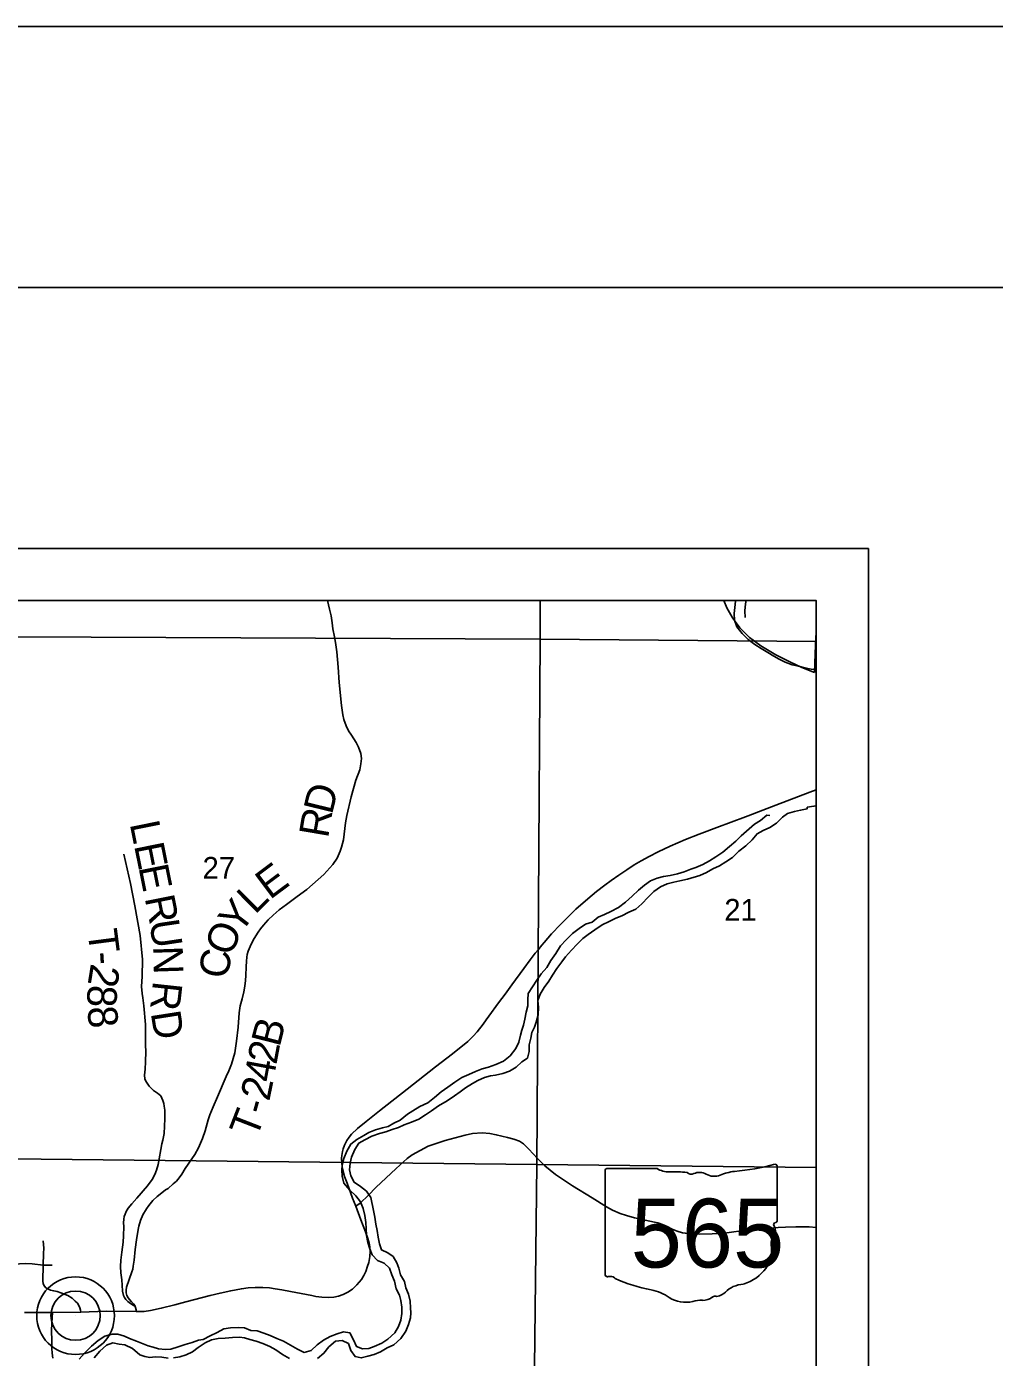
# Model space of a CAD drawing. Extents: x 0 to 34, y 0 to 22.
# Drawn here: x 7.387 to 9.241, y 19.45 to 22 of the extents above; entities that cross this region are included whole.
import ezdxf

# ---------------------------------------------------------------- set-up
doc = ezdxf.new("R2010")
doc.units = 0
for name, color, linetype in [('GM_X_Corporation', 7, 'Continuous'), ('GM_X_County_Road', 7, 'Continuous'), ('GM_X_Major_River', 7, 'Continuous'), ('GM_X_Section_Text', 7, 'Continuous'), ('GM_X_State_Route', 7, 'Continuous'), ('GM_X_State_Shield', 7, 'Continuous'), ('GM_X_Township_Road', 7, 'Continuous'), ('GM_X_Township_Road_Text', 7, 'Continuous'), ('GM_X_Township_Text', 7, 'Continuous'), ('GM_X_Unincorporated', 7, 'Continuous'), ('GM_X_Unincorporated_Location', 7, 'Continuous'), ('SH_Border', 7, 'Continuous'), ('SH_Cut_Line', 7, 'Continuous'), ('SH_Data', 7, 'Continuous')]:
    doc.layers.add(name, color=color, linetype=linetype)

msp = doc.modelspace()

# ---------------------------------------------------------------- linework, layer by layer
at = {"layer": 'GM_X_Corporation'}
for points in [[(8.371, 20.9), (7.3671, 20.9), (7.3663, 20.8308), (8.3706, 20.8258)], [(8.9, 20.8218), (8.9, 20.9), (8.371, 20.9), (8.3706, 20.8258)], [(8.3706, 20.8258), (8.3645, 19.8193), (7.3548, 19.8302), (7.3663, 20.8308)], [(8.9, 19.8133), (8.9, 20.8218), (8.3706, 20.8258), (8.3645, 19.8193)], [(8.3645, 19.8193), (8.353, 18.8213), (7.3418, 18.8315), (7.3548, 19.8302)], [(8.9, 18.8136), (8.9, 19.8133), (8.3645, 19.8193), (8.353, 18.8213)]]:
    msp.add_lwpolyline(points, close=True, dxfattribs=at)
at = {"layer": 'GM_X_County_Road'}
msp.add_lwpolyline([(7.4367, 19.4485), (7.4357, 19.4575), (7.4351, 19.4669), (7.4346, 19.482), (7.4342, 19.5004), (7.4347, 19.515), (7.4359, 19.5357)], dxfattribs=at)
at = {"layer": 'GM_X_Major_River'}
for points in [[(8.7457, 20.9), (8.7454, 20.8989), (8.7437, 20.8867), (8.7423, 20.8753), (8.7432, 20.8624), (8.7475, 20.8496), (8.7578, 20.8372), (8.7693, 20.8255), (8.7819, 20.8158), (8.7945, 20.8084), (8.8071, 20.8005), (8.8189, 20.7935), (8.8288, 20.7879), (8.8406, 20.7823), (8.8535, 20.7771), (8.866, 20.7742), (8.8778, 20.7713)], [(8.7636, 20.8676), (8.7627, 20.8805), (8.764, 20.8938), (8.7657, 20.9)], [(8.8778, 20.7713), (8.8903, 20.7688), (8.9, 20.7681)], [(8.8822, 20.504), (8.8954, 20.506), (8.9, 20.5068)], [(8.8112, 20.4884), (8.8052, 20.4891), (8.7932, 20.4788), (8.7815, 20.4714), (8.756, 20.4492), (8.7459, 20.4388), (8.7339, 20.4288), (8.7208, 20.4181), (8.7073, 20.4088), (8.6952, 20.4015), (8.6825, 20.3942), (8.6693, 20.3884), (8.6595, 20.3856), (8.647, 20.3802), (8.6338, 20.3766), (8.6199, 20.373), (8.6074, 20.3714), (8.5953, 20.3682), (8.5825, 20.3628), (8.5709, 20.3547), (8.5592, 20.3451), (8.5472, 20.3336), (8.5341, 20.3221), (8.5206, 20.3121), (8.5059, 20.304), (8.4939, 20.2982), (8.4818, 20.2935), (8.4702, 20.2839), (8.4578, 20.2799), (8.4457, 20.2719), (8.433, 20.2619), (8.4206, 20.25), (8.4098, 20.2381), (8.4005, 20.224), (8.3912, 20.2102), (8.3834, 20.1972), (8.3729, 20.1846), (8.3643, 20.1724), (8.348, 20.1472), (8.3473, 20.1351), (8.3471, 20.1237), (8.3442, 20.1111), (8.3413, 20.0978), (8.3388, 20.0864), (8.3359, 20.0769), (8.3333, 20.067), (8.3297, 20.0537), (8.3241, 20.0415), (8.3133, 20.0277), (8.3002, 20.0177), (8.2855, 20.0108), (8.2719, 20.0057), (8.2598, 20.0025), (8.2466, 19.9978), (8.2338, 19.992), (8.2207, 19.9858), (8.2075, 19.977), (8.194, 19.9673), (8.1809, 19.9585), (8.1685, 19.9477), (8.1553, 19.9377), (8.1403, 19.9304), (8.1264, 19.9219), (8.1166, 19.9157), (8.1027, 19.9042), (8.0903, 19.8987), (8.0794, 19.8925), (8.0688, 19.8894), (8.0549, 19.8858), (8.0424, 19.8804), (8.0327, 19.875), (8.0191, 19.8673), (8.0079, 19.8584), (8.0001, 19.8447), (7.9945, 19.8306), (7.9913, 19.8188), (7.9906, 19.8086), (7.9911, 19.7968), (7.9947, 19.7836), (8.0058, 19.7704), (8.0173, 19.7595), (8.0261, 19.7479), (8.0315, 19.735), (8.0347, 19.7218), (8.0364, 19.7085), (8.0373, 19.6964), (8.0382, 19.6831), (8.0402, 19.6699), (8.0441, 19.6578), (8.0488, 19.6461), (8.0591, 19.6352), (8.072, 19.63), (8.082, 19.621), (8.0867, 19.6082), (8.0913, 19.5957), (8.0945, 19.5813), (8.1011, 19.5689), (8.1039, 19.5587), (8.1059, 19.5462), (8.1056, 19.5337), (8.1035, 19.5211)], [(8.0998, 19.6208), (8.0963, 19.631), (8.0889, 19.6431), (8.0786, 19.6498), (8.0665, 19.6558), (8.0629, 19.6675), (8.0605, 19.68), (8.0585, 19.6928), (8.0557, 19.7049), (8.054, 19.7186), (8.0513, 19.7311), (8.0464, 19.756), (8.0376, 19.7685), (8.0265, 19.7771), (8.0143, 19.7853), (8.0078, 19.7977), (8.0054, 19.8091), (8.0064, 19.822), (8.0093, 19.8334), (8.0155, 19.8483), (8.023, 19.8605), (8.035, 19.8667), (8.0482, 19.8736), (8.0629, 19.8787), (8.075, 19.8819), (8.0874, 19.8862), (8.0995, 19.8905), (8.1104, 19.8955), (8.124, 19.9002), (8.1383, 19.9064), (8.1511, 19.9145), (8.1623, 19.9219), (8.1762, 19.9315), (8.1924, 19.9411), (8.2063, 19.9508), (8.2176, 19.9589), (8.2277, 19.9662), (8.2408, 19.9746), (8.251, 19.9804), (8.2638, 19.9859), (8.2755, 19.9894), (8.2853, 19.9907), (8.2989, 19.9935), (8.3121, 19.9982), (8.3249, 20.0062), (8.3354, 20.0158), (8.3463, 20.0232), (8.3495, 20.0361), (8.3494, 20.0486), (8.3527, 20.0612), (8.3548, 20.0726), (8.36, 20.0825), (8.3633, 20.092), (8.3669, 20.1061), (8.3675, 20.1205), (8.3666, 20.1337), (8.3707, 20.1455), (8.3785, 20.1585), (8.3871, 20.1707), (8.3945, 20.1822), (8.4027, 20.1952), (8.412, 20.2078), (8.4191, 20.2173), (8.4311, 20.23), (8.4415, 20.2415), (8.4528, 20.2522), (8.4625, 20.2599), (8.4753, 20.2691), (8.4896, 20.2788), (8.5027, 20.2853), (8.5155, 20.2912), (8.5276, 20.2962), (8.5408, 20.3028), (8.554, 20.3086), (8.5656, 20.3186), (8.5775, 20.3316), (8.5884, 20.3428), (8.6015, 20.3516), (8.614, 20.3571), (8.6268, 20.3602), (8.6385, 20.363), (8.6529, 20.3662), (8.677, 20.3733), (8.6898, 20.3787), (8.7018, 20.386), (8.7143, 20.3915), (8.7267, 20.3996), (8.7394, 20.4077), (8.7514, 20.4196), (8.7649, 20.4303), (8.7773, 20.4418), (8.7866, 20.4533), (8.7979, 20.4595), (8.8107, 20.4649), (8.8235, 20.4734), (8.8351, 20.4853), (8.8449, 20.4922), (8.8581, 20.4958), (8.8698, 20.4982), (8.8822, 20.5009), (8.8822, 20.504)], [(7.9442, 19.4474), (7.9562, 19.4578), (7.9659, 19.47), (7.9787, 19.4808), (7.9912, 19.482), (8.0033, 19.4761), (8.008, 19.4629), (8.0161, 19.4512), (8.0279, 19.4487), (8.0403, 19.4518), (8.0524, 19.4554), (8.0648, 19.4604), (8.0776, 19.4681), (8.0904, 19.4736), (8.1039, 19.4859), (8.1136, 19.5), (8.1184, 19.5129), (8.122, 19.5255), (8.1227, 19.535), (8.1222, 19.5445), (8.1217, 19.5574), (8.1181, 19.571), (8.1134, 19.5827), (8.1106, 19.5952), (8.1029, 19.608), (8.0998, 19.6208)], [(8.1035, 19.5211), (8.0995, 19.509), (8.0924, 19.4967), (8.0789, 19.4845), (8.0673, 19.4771), (8.0526, 19.4705), (8.0424, 19.4666), (8.0303, 19.4661), (8.0185, 19.4706), (8.0131, 19.4834), (8.0061, 19.4966), (7.9936, 19.4987), (7.9816, 19.4948), (7.968, 19.4897), (7.9556, 19.4828), (7.9436, 19.4739), (7.9316, 19.4628), (7.9184, 19.4593), (7.9054, 19.4652), (7.8925, 19.473), (7.8788, 19.4805), (7.8659, 19.4856), (7.8533, 19.4919), (7.8411, 19.4964), (7.8282, 19.5004), (7.8161, 19.5014), (7.8043, 19.5066), (7.7918, 19.5068), (7.7775, 19.5063), (7.7642, 19.5043), (7.7514, 19.4973), (7.7383, 19.4911), (7.7247, 19.4838), (7.7157, 19.4825), (7.7036, 19.4782), (7.6904, 19.4747), (7.6772, 19.47), (7.6629, 19.4657), (7.653, 19.4648), (7.6394, 19.4662), (7.6291, 19.4691), (7.6197, 19.472), (7.6102, 19.4757), (7.5969, 19.4805), (7.5839, 19.4861), (7.5744, 19.4905), (7.5615, 19.4942), (7.5502, 19.4944), (7.5362, 19.4901), (7.5234, 19.482), (7.5111, 19.4713), (7.4972, 19.4578), (7.4875, 19.446)], [(7.668, 19.4486), (7.6801, 19.4507), (7.6921, 19.4546), (7.7045, 19.4604), (7.7151, 19.4685), (7.729, 19.4774), (7.741, 19.4832), (7.7538, 19.4856), (7.7671, 19.4865), (7.7814, 19.4878), (7.7947, 19.4883), (7.8042, 19.4873), (7.814, 19.4839), (7.8262, 19.4807), (7.8395, 19.4763), (7.8524, 19.4707), (7.8642, 19.464), (7.8768, 19.4554), (7.8905, 19.4476)], [(7.5162, 19.4489), (7.527, 19.4619), (7.5394, 19.4731), (7.5515, 19.4778), (7.5636, 19.4752), (7.5746, 19.4738), (7.5894, 19.4668), (7.6036, 19.4548), (7.6131, 19.4515), (7.6229, 19.4493), (7.6331, 19.4506), (7.6456, 19.4499), (7.6581, 19.4485)]]:
    msp.add_lwpolyline(points, dxfattribs=at)
at = {"layer": 'GM_X_State_Route'}
for points in [[(8.8966, 20.762), (8.872, 20.7718), (8.8493, 20.7824), (8.8223, 20.796), (8.7935, 20.8134), (8.7722, 20.8295), (8.7623, 20.8387), (8.7534, 20.8481), (8.7443, 20.8601), (8.7388, 20.8684), (8.7286, 20.8862), (8.7226, 20.9)], [(8.9, 20.8366), (8.8994, 20.8312), (8.8981, 20.7979), (8.8971, 20.7799), (8.8966, 20.762)], [(8.3668, 20.2309), (8.374, 20.24), (8.3785, 20.245), (8.3926, 20.2613), (8.4096, 20.2794), (8.4248, 20.2945), (8.4393, 20.3086), (8.4619, 20.3286), (8.4785, 20.3423), (8.4944, 20.3545), (8.5066, 20.3633), (8.5216, 20.3737), (8.537, 20.3842), (8.5509, 20.3935), (8.5642, 20.4014), (8.5797, 20.4095), (8.597, 20.4183), (8.6201, 20.4291), (8.6495, 20.4421), (8.6756, 20.4522), (8.7146, 20.4673), (8.7315, 20.4734), (8.7696, 20.4876), (8.7978, 20.4984), (8.8227, 20.5081), (8.8877, 20.5326), (8.9, 20.5372)], [(8.2723, 20.1037), (8.291, 20.1289), (8.3037, 20.1459), (8.3165, 20.1635), (8.3397, 20.1951), (8.3514, 20.2115), (8.3614, 20.2242), (8.3668, 20.2309)], [(8.0175, 19.7393), (8.0111, 19.7551), (8.0006, 19.7833), (7.9958, 19.7966), (7.992, 19.8109), (7.9911, 19.8154), (7.9904, 19.8222), (7.9903, 19.8313), (7.9906, 19.8368), (7.9918, 19.844), (7.993, 19.8497), (7.9955, 19.8566), (8.0004, 19.8654), (8.0045, 19.8717), (8.0093, 19.8776), (8.0207, 19.8882), (8.0373, 19.9018), (8.0631, 19.9221), (8.116, 19.9635), (8.1704, 20.0064), (8.2029, 20.0317), (8.2319, 20.0551), (8.2426, 20.0652), (8.25, 20.0737), (8.2612, 20.0884), (8.2671, 20.0966), (8.2723, 20.1037)], [(8.0175, 19.7393), (8.0258, 19.7455), (8.042, 19.7606), (8.056, 19.7753), (8.095, 19.8115), (8.1157, 19.8309), (8.1252, 19.8378), (8.1558, 19.8543), (8.1885, 19.8655), (8.227, 19.8756), (8.2413, 19.8789), (8.2595, 19.8802), (8.2742, 19.8787), (8.2866, 19.8763), (8.3079, 19.8712), (8.3205, 19.868), (8.3309, 19.864), (8.3387, 19.8592), (8.3433, 19.8548), (8.3491, 19.8488), (8.3654, 19.8309), (8.3799, 19.8167), (8.4004, 19.8003), (8.4327, 19.7786), (8.4706, 19.7552), (8.4979, 19.738), (8.5095, 19.7318), (8.524, 19.7254), (8.5361, 19.7214), (8.5515, 19.7173), (8.566, 19.7137), (8.5808, 19.7108), (8.5898, 19.7091), (8.596, 19.7074), (8.6051, 19.7046), (8.614, 19.7008), (8.624, 19.6955), (8.6332, 19.6914), (8.6434, 19.6886), (8.649, 19.6876), (8.6565, 19.6867), (8.6756, 19.6859), (8.7007, 19.6863), (8.7192, 19.6871), (8.7558, 19.692), (8.7824, 19.6951), (8.8029, 19.6969), (8.8272, 19.6987), (8.8412, 19.6994), (8.8605, 19.6996), (8.886, 19.6996), (8.9, 19.6989)], [(7.3822, 19.5358), (7.4105, 19.5358), (7.4359, 19.5357), (7.4903, 19.5363), (7.5387, 19.538), (7.5966, 19.5374), (7.6115, 19.5378), (7.6241, 19.5397), (7.6447, 19.544), (7.6706, 19.5507), (7.6917, 19.5563), (7.7386, 19.5683), (7.7572, 19.5729), (7.7776, 19.5775), (7.7981, 19.5811), (7.8113, 19.5827), (7.8244, 19.5835), (7.8392, 19.5835), (7.8518, 19.5827), (7.863, 19.5813), (7.8754, 19.5793), (7.8922, 19.5761), (7.9331, 19.5682), (7.941, 19.5666), (7.9526, 19.565), (7.9654, 19.5644), (7.9755, 19.5654), (7.9841, 19.567), (7.9935, 19.5701), (8.0024, 19.5745), (8.0113, 19.5805), (8.0197, 19.5887), (8.024, 19.5936), (8.0282, 19.5989), (8.0329, 19.6066), (8.0364, 19.6142), (8.0401, 19.6244), (8.0421, 19.6318), (8.044, 19.6428), (8.0448, 19.6531), (8.0442, 19.6614), (8.0429, 19.6689), (8.0407, 19.6775), (8.0362, 19.6902), (8.0273, 19.7135), (8.0175, 19.7393)]]:
    msp.add_lwpolyline(points, dxfattribs=at)
at = {"layer": 'GM_X_State_Shield'}
for p, q in [((8.8248, 19.7117), (8.8248, 19.8164)), ((8.4952, 19.808), (8.4952, 19.6079)), ((8.595, 19.8115), (8.4984, 19.8115)), ((8.8247, 19.7118), (8.8248, 19.7117))]:
    msp.add_line(p, q, dxfattribs=at)
for centre, major_axis, start_param, end_param in [((8.7074, 20.0843), (0.3495, 0), 4.814394, 5.042369), ((8.8211, 19.8169), (0.00367, 0), 6.141152, 7.989035), ((8.499, 19.8085), (0.00382, 0), 1.712693, 3.28349), ((8.6179, 19.8347), (0.037, 0), 4.042523, 4.731795), ((8.6302, 19.6991), (0.133, 0), 1.404758, 1.657858), ((8.6604, 19.8095), (0.0107, 0), 3.836095, 5.185415), ((8.6761, 19.7864), (0.0222, 0), 0.950623, 2.079405), ((8.7048, 19.8181), (0.0267, 0), 4.081561, 5.145723), ((8.752, 19.7503), (0.0703, 0), 1.699011, 2.107814), ((8.8239, 19.7041), (0.00568, 0), 1.883978, 3.671073), ((8.7878, 19.6908), (0.0341, 0), 5.934695, 6.695948), ((8.8209, 19.7113), (0.00393, 0), 5.05454, 6.418171), ((8.727, 19.6546), (0.0874, 0), 5.101752, 6.440018), ((8.8379, 19.6679), (0.0248, 0), 2.387724, 3.262537), ((8.499, 19.6075), (0.00385, 0), 3.00124, 4.508301), ((8.4996, 19.6279), (0.0294, 0), 4.665946, 4.897461), ((8.5056, 19.5964), (0.0106, 0), 0.519207, 1.627899), ((8.6394, 19.7762), (0.2524, 0), 4.195997, 4.488961), ((8.7638, 19.5517), (0.0479, 0), 1.647645, 2.488434), ((8.5642, 19.518), (0.079, 0), 0.823519, 1.323587), ((8.6496, 19.5954), (0.0501, 0), 4.026481, 4.996735), ((8.6822, 19.5804), (0.0267, 0), 4.691044, 5.507374), ((8.7064, 19.561), (0.00752, 0), 1.147584, 2.315152), ((8.7032, 19.5885), (0.0282, 0), 4.937069, 5.64225), ((8.6785, 19.5262), (0.0412, 0), 1.495662, 1.94098)]:
    msp.add_ellipse(centre, major_axis=major_axis, ratio=0.8, start_param=start_param, end_param=end_param, dxfattribs=at)
at = {"layer": 'GM_X_Township_Road'}
for points in [[(7.5966, 19.5374), (7.5964, 19.5408), (7.5954, 19.545), (7.5948, 19.547), (7.5937, 19.5493), (7.5912, 19.5525), (7.5877, 19.5564), (7.5839, 19.5605), (7.5812, 19.5638), (7.5786, 19.5683), (7.5775, 19.5732), (7.5773, 19.5786), (7.578, 19.5842), (7.5884, 19.6136), (7.5898, 19.619), (7.5908, 19.6243), (7.5924, 19.636), (7.5946, 19.6567), (7.5971, 19.6751), (7.6001, 19.6948), (7.6014, 19.7013), (7.605, 19.7123), (7.6093, 19.7227), (7.6162, 19.7347), (7.6208, 19.741), (7.626, 19.7473), (7.6286, 19.7505), (7.637, 19.7579), (7.6489, 19.7675), (7.653, 19.7705), (7.6575, 19.7736), (7.6676, 19.7822), (7.6737, 19.7877), (7.6762, 19.7904), (7.6788, 19.7938), (7.684, 19.8007), (7.6905, 19.8116), (7.7089, 19.8388), (7.7158, 19.8513), (7.7237, 19.8695), (7.7284, 19.8838), (7.7344, 19.9051), (7.7375, 19.9144), (7.744, 19.9298), (7.7525, 19.9492), (7.7691, 19.9877), (7.774, 19.9987), (7.7791, 20.0118), (7.7825, 20.0224), (7.7854, 20.0336), (7.789, 20.0559), (7.7919, 20.0828), (7.7937, 20.1102), (7.7961, 20.1232), (7.7994, 20.1368), (7.8026, 20.1503), (7.8045, 20.1609), (7.8059, 20.1718), (7.8066, 20.1815), (7.807, 20.1984), (7.8078, 20.2088), (7.8085, 20.2167), (7.8095, 20.2221), (7.8109, 20.2279), (7.8147, 20.2374), (7.8185, 20.2452), (7.8224, 20.2524), (7.8304, 20.2645), (7.835, 20.2707), (7.8407, 20.2781), (7.8494, 20.2882), (7.8588, 20.2974), (7.8703, 20.3071), (7.8843, 20.3179), (7.9048, 20.3327), (7.9237, 20.3465), (7.9559, 20.375), (7.9734, 20.3942), (7.9818, 20.4064), (7.9876, 20.4198), (7.9902, 20.4272), (7.9936, 20.4415), (7.9978, 20.474), (8.0004, 20.4884), (8.0083, 20.5239), (8.0172, 20.5559), (8.025, 20.5757), (8.0273, 20.587), (8.0282, 20.5977), (8.0272, 20.6071), (8.0227, 20.619), (8.0178, 20.6282), (8.0094, 20.642), (8.0034, 20.6506), (7.9988, 20.66), (7.9945, 20.672), (7.9928, 20.6808), (7.99, 20.6987), (7.9857, 20.7433), (7.9835, 20.7723), (7.9812, 20.8018), (7.9783, 20.8197), (7.9764, 20.8307), (7.9732, 20.8457), (7.9719, 20.8572), (7.9701, 20.8706), (7.9672, 20.8838), (7.9631, 20.9)], [(7.5948, 19.547), (7.5904, 19.5499), (7.5858, 19.5527), (7.5806, 19.557), (7.5767, 19.5608), (7.574, 19.5648), (7.5722, 19.5686), (7.5705, 19.5765), (7.5699, 19.5883), (7.5688, 19.5986), (7.5674, 19.6116), (7.5664, 19.6236), (7.5673, 19.636), (7.5687, 19.6515), (7.5713, 19.6707), (7.5724, 19.6829), (7.5726, 19.7006), (7.5724, 19.7076), (7.5727, 19.7147), (7.5737, 19.7194), (7.5751, 19.724), (7.5776, 19.7296), (7.5813, 19.7359), (7.588, 19.7442), (7.5977, 19.7551), (7.6183, 19.7782), (7.6269, 19.7906), (7.6322, 19.8004), (7.6356, 19.8086), (7.6389, 19.8194), (7.6455, 19.859), (7.6475, 19.8663), (7.6502, 19.8785), (7.6512, 19.907), (7.6515, 19.9146), (7.6514, 19.9233), (7.6504, 19.931), (7.6493, 19.9362), (7.6475, 19.942), (7.6459, 19.9465), (7.6436, 19.9507), (7.6408, 19.9532), (7.6374, 19.9558), (7.6296, 19.9614), (7.625, 19.9657), (7.6215, 19.9694), (7.615, 19.9789), (7.6129, 19.9838), (7.6127, 19.9906), (7.6138, 20.0021), (7.6146, 20.0158), (7.6147, 20.0357), (7.6142, 20.0478), (7.6145, 20.0637), (7.6144, 20.0876), (7.611, 20.1234), (7.6093, 20.1386), (7.608, 20.147), (7.607, 20.1606), (7.608, 20.1799), (7.6085, 20.2122), (7.6042, 20.258), (7.5938, 20.3148), (7.5855, 20.358), (7.5728, 20.4141)], [(7.4354, 19.6262), (7.4181, 19.6264), (7.397, 19.6293), (7.3853, 19.6296), (7.3731, 19.629), (7.3671, 19.6286), (7.3629, 19.6292), (7.3576, 19.6319), (7.3561, 19.6347), (7.3549, 19.6397), (7.3547, 19.6516), (7.355, 19.6572), (7.3556, 19.663)], [(7.4903, 19.5363), (7.4899, 19.5401), (7.4887, 19.5447), (7.4868, 19.549), (7.4838, 19.5537), (7.4798, 19.5577), (7.4736, 19.5629), (7.4657, 19.568), (7.4521, 19.5737), (7.4453, 19.5759), (7.4386, 19.5772), (7.4325, 19.5787), (7.4272, 19.5808), (7.4231, 19.5831), (7.4205, 19.5861), (7.4183, 19.5904), (7.4175, 19.5962), (7.4181, 19.6264), (7.4191, 19.6487), (7.4195, 19.6589), (7.4185, 19.6728)]]:
    msp.add_lwpolyline(points, dxfattribs=at)
at = {"layer": 'GM_X_Township_Text'}
msp.add_lwpolyline([(8.9, 16.8499), (8.9, 20.9), (6.4827, 20.9)], dxfattribs=at)
at = {"layer": 'GM_X_Unincorporated'}
for radius in [0.0744, 0.0472]:
    msp.add_circle((7.4804, 19.5297), radius, dxfattribs=at)
at = {"layer": 'GM_X_Unincorporated_Location'}
msp.add_line((7.4804, 19.5297), (7.4804, 19.5297), dxfattribs=at)
at = {"layer": 'SH_Border'}
msp.add_lwpolyline([(1.5, 21.5), (33.5, 21.5), (33.5, 0.5), (1.5, 0.5)], close=True, dxfattribs=at)
at = {"layer": 'SH_Cut_Line'}
msp.add_lwpolyline([(0, 0), (34, 0), (34, 22), (0, 22)], close=True, dxfattribs=at)
at = {"layer": 'SH_Data'}
for p, q in [((2, 21), (9, 21)), ((9, 21), (9, 14)), ((2.1, 20.9), (8.9, 20.9)), ((8.9, 20.9), (8.9, 14.1))]:
    msp.add_line(p, q, dxfattribs=at)

# ---------------------------------------------------------------- texts
at = {"layer": 'GM_X_Section_Text'}
for s, p in [('27', (7.7237, 20.3669)), ('21', (8.7237, 20.2864))]:
    msp.add_text(s, height=0.04186, rotation=0, dxfattribs=at).set_placement(p)
at = {"layer": 'GM_X_State_Shield'}
msp.add_text('565', height=0.13184, dxfattribs=at).set_placement((8.5443, 19.622))
at = {"layer": 'GM_X_Township_Road_Text'}
for s, rotation, p in [('D', 76.3154, (7.9717, 20.4883)), ('R', 80.3375, (7.9641, 20.4434)), ('L', 281.4326, (7.5839, 20.4724)), ('E', 281.4324, (7.5923, 20.4308)), ('E', 281.4324, (7.6007, 20.3891)), ('E', 36.7439, (7.8528, 20.3258)), ('R', 281.3023, (7.6126, 20.3304)), ('Y', 52.8992, (7.7954, 20.259)), ('L', 44.5757, (7.8241, 20.2973)), ('U', 278.4676, (7.6216, 20.2853)), ('O', 67.6351, (7.7783, 20.2161)), ('T', 277.4264, (7.503, 20.267)), ('-', 273.4916, (7.5084, 20.2259)), ('N', 271.8436, (7.6288, 20.2376)), ('C', 80.555, (7.7716, 20.1734)), ('2', 260.9278, (7.51, 20.2059)), ('8', 267.5386, (7.5037, 20.1642)), ('R', 263.8175, (7.629, 20.1723)), ('8', 275.6213, (7.5025, 20.1205)), ('D', 278.8489, (7.6243, 20.11)), ('B', 75.6551, (7.8713, 20.0428)), ('2', 79.38, (7.8651, 20.0093)), ('4', 79.6127, (7.8588, 19.9749)), ('2', 78.2295, (7.8514, 19.9392)), ('T', 68.7979, (7.8268, 19.8674)), ('-', 74.2632, (7.844, 19.9126))]:
    msp.add_text(s, height=0.0568, rotation=rotation, dxfattribs=at).set_placement(p)

doc.saveas('drawing.dxf')
